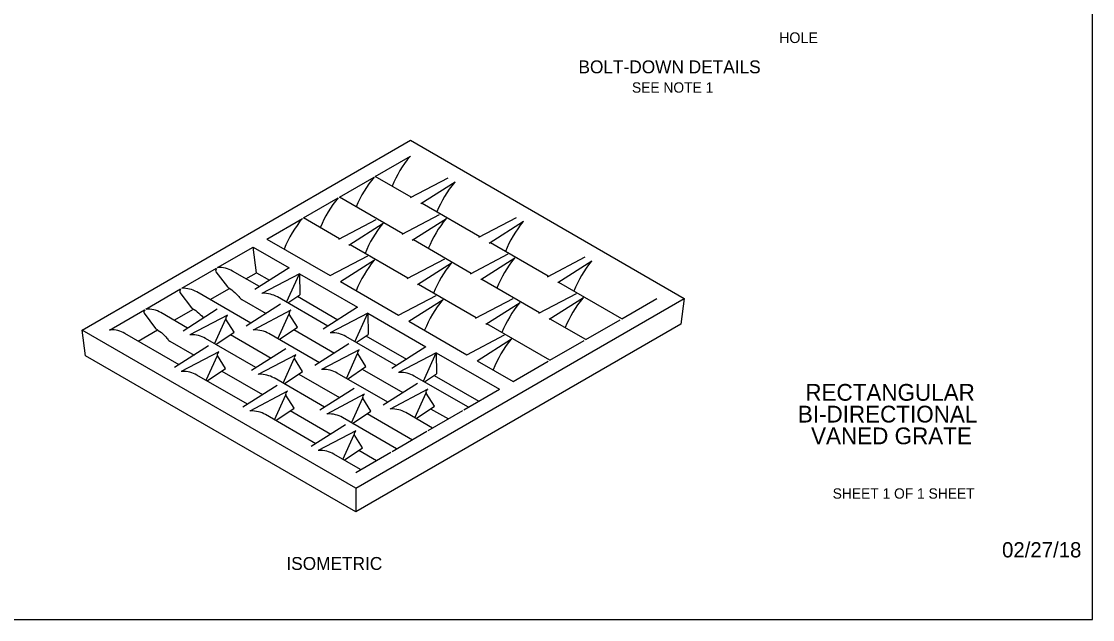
# Model space of a CAD drawing. Extents: x 99862 to 103151, y 100000 to 102076.
# Drawn here: x 101491 to 103151, y 100000 to 100926 of the extents above; entities that cross this region are included whole.
import ezdxf

# ---------------------------------------------------------------- set-up
doc = ezdxf.new("R2010")
doc.units = 0
for name, color, linetype in [('Level 1', 7, 'Continuous'), ('Level 15', 7, 'Continuous'), ('Level 20', 7, 'Continuous'), ('Level 27', 7, 'Continuous'), ('Level 6', 7, 'Continuous'), ('Level 62', 7, 'Continuous')]:
    doc.layers.add(name, color=color, linetype=linetype)

msp = doc.modelspace()

# ---------------------------------------------------------------- linework, layer by layer
at = {"layer": 'Level 1'}
msp.add_lwpolyline([(99862, 99999.5), (103151, 99999.5), (103151, 102075.5), (99862, 102075.5)], close=True, dxfattribs=at)
at = {"layer": 'Level 27'}
for p, q in [((101901.7, 100491.1), (101921.6, 100535.3)), ((102007.8, 100429.9), (102027.6, 100474.1)), ((101790.3, 100426.8), (101807.7, 100465.5)), ((101888.4, 100434.5), (101905.8, 100473.1)), ((101777.1, 100370.2), (101794.5, 100408.8)), ((101994.5, 100373.2), (102011.9, 100411.9)), ((102113.8, 100368.7), (102133.7, 100412.9)), ((101896.4, 100365.6), (101913.8, 100404.2)), ((101883.1, 100308.9), (101900.5, 100347.6)), ((102002.5, 100304.4), (102019.8, 100343)), ((102100.6, 100312), (102118, 100350.7)), ((101989.2, 100247.7), (102006.6, 100286.4))]:
    msp.add_line(p, q, dxfattribs=at)
at = {"layer": 'Level 6'}
for p, q in [((102039.3, 100686), (102093.9, 100717.5)), ((101983.7, 100653.8), (102037.7, 100685)), ((102095.1, 100653.8), (102039.3, 100686)), ((102093.9, 100653.2), (102152.3, 100683.8)), ((102109.8, 100644), (102162.9, 100677.7)), ((101928, 100621.7), (101982, 100652.9)), ((102081.8, 100597.2), (101983.7, 100653.8)), ((102201.2, 100592.6), (102111.7, 100644.2)), ((102080.7, 100596.6), (102139, 100627.2)), ((101871.2, 100588.9), (101926.3, 100620.7)), ((101983.7, 100589.5), (101928, 100621.7)), ((101982.6, 100588.9), (102040.9, 100619.5)), ((101998.5, 100579.7), (102051.5, 100613.4)), ((102096.6, 100587.4), (102149.6, 100621.1)), ((102200, 100592), (102258.3, 100622.6)), ((102215.9, 100582.8), (102268.9, 100616.5)), ((101794.9, 100544.8), (101850, 100576.7)), ((101850, 100576.7), (101905.7, 100544.5)), ((101855.3, 100536.9), (101850, 100576.7)), ((101871.2, 100588.9), (101969.3, 100532.3)), ((102089.8, 100528.3), (102000.3, 100579.9)), ((102187.9, 100535.9), (102098.4, 100587.6)), ((102307.2, 100531.3), (102217.7, 100583)), ((101969.3, 100532.3), (102027.6, 100562.9)), ((101985.2, 100523.1), (102038.3, 100556.8)), ((102088.6, 100527.7), (102147, 100558.3)), ((102186.7, 100535.3), (102245.1, 100565.9)), ((102202.7, 100526.1), (102255.7, 100559.8)), ((102306.1, 100530.7), (102364.4, 100561.4)), ((101739.2, 100512.7), (101793.2, 100543.9)), ((101905.7, 100544.5), (101852.6, 100510.8)), ((102104.5, 100518.5), (102157.6, 100552.2)), ((102322, 100521.6), (102375, 100555.2)), ((101792.3, 100538.4), (101810.1, 100514.9)), ((101859.7, 100515.4), (101818.2, 100539.3)), ((101838.9, 100527.4), (101855.3, 100536.9)), ((101855.3, 100536.9), (101875.4, 100525.3)), ((101921.6, 100535.3), (101863.2, 100504.7)), ((101921.6, 100535.3), (102011.7, 100483.3)), ((101921.6, 100535.3), (101922.1, 100502.7)), ((101985.2, 100523.1), (102075.4, 100471)), ((102294, 100474.7), (102204.5, 100526.4)), ((101683.5, 100480.5), (101737.5, 100511.7)), ((101846.5, 100458.7), (101762.5, 100507.2)), ((101783.2, 100495.2), (101813.3, 100512.6)), ((102195.8, 100467), (102106.4, 100518.7)), ((102421.2, 100465.5), (102323.8, 100521.8)), ((101736.6, 100506.3), (101754.4, 100482.7)), ((101832.3, 100495.2), (101869.9, 100473.5)), ((101965.8, 100454.1), (101887.6, 100499.3)), ((101903.5, 100490.1), (101922.1, 100502.7)), ((101918.6, 100500.3), (101981.4, 100464)), ((102009.1, 100203.1), (102518.2, 100497.1)), ((102075.4, 100471), (102133.7, 100501.6)), ((102091.3, 100461.8), (102144.3, 100495.5)), ((102194.7, 100466.4), (102253, 100497.1)), ((102210.6, 100457.3), (102263.6, 100490.9)), ((102292.8, 100474.1), (102351.1, 100504.7)), ((102308.7, 100464.9), (102361.8, 100498.6)), ((102421.2, 100465.5), (102475.8, 100497.1)), ((101627.2, 100448.1), (101681.8, 100479.6)), ((101680.9, 100474.1), (101698.7, 100450.6)), ((101748.4, 100451.1), (101706.8, 100475)), ((101727.5, 100463.1), (101757.6, 100480.4)), ((101794.3, 100480.2), (101741.3, 100446.5)), ((101892.4, 100487.9), (101839.4, 100454.2)), ((101908.3, 100478.7), (101850, 100448.1)), ((102011.7, 100483.3), (101958.7, 100449.6)), ((102027.6, 100474.1), (101969.3, 100443.5)), ((102027.6, 100474.1), (102117.8, 100422)), ((102027.6, 100474.1), (102028.2, 100441.4)), ((101810.2, 100471), (101751.9, 100440.4)), ((101820.5, 100445), (101807.9, 100465.1)), ((101918.6, 100452.6), (101906, 100472.8)), ((102091.3, 100461.8), (102181.4, 100409.8)), ((102309.8, 100401.2), (102212.4, 100457.5)), ((102365.5, 100433.4), (102310.5, 100465.1)), ((102365.5, 100433.4), (102418.7, 100464.1)), ((102009.1, 100203.1), (101584.8, 100448.1)), ((101735.1, 100394.4), (101651.2, 100442.9)), ((101671.8, 100430.9), (101701.9, 100448.3)), ((101792.1, 100425.8), (101820.5, 100445)), ((101814.7, 100441.1), (101877.8, 100404.7)), ((101952.6, 100397.5), (101874.3, 100442.6)), ((101890.2, 100433.5), (101918.6, 100452.6)), ((101912.9, 100448.7), (101975.9, 100412.3)), ((102009.5, 100428.9), (102028.2, 100441.4)), ((102181.4, 100409.8), (102239.8, 100440.4)), ((101720.9, 100430.9), (101758.5, 100409.2)), ((101781, 100423.6), (101728, 100389.9)), ((101854.4, 100389.8), (101776.2, 100435)), ((101998.5, 100426.6), (101945.4, 100393)), ((102071.9, 100392.9), (101993.6, 100438.1)), ((102024.7, 100439.1), (102087.5, 100402.8)), ((102197.4, 100400.6), (102250.4, 100434.3)), ((102309.8, 100401.2), (102363.1, 100432)), ((101797, 100414.4), (101738.6, 100383.8)), ((101807.2, 100388.3), (101794.6, 100408.5)), ((101900.4, 100419), (101847.3, 100385.3)), ((101916.3, 100409.8), (101857.9, 100379.2)), ((102014.4, 100417.4), (101956.1, 100386.8)), ((102024.7, 100391.4), (102012.1, 100411.6)), ((102117.8, 100422), (102064.8, 100388.4)), ((102133.7, 100412.9), (102075.4, 100382.2)), ((102133.7, 100412.9), (102231.8, 100356.2)), ((102133.7, 100412.9), (102134.2, 100380.2)), ((101926.6, 100383.7), (101913.9, 100403.9)), ((101996.3, 100372.2), (102024.7, 100391.4)), ((102197.4, 100400.6), (102253, 100368.5)), ((102253, 100368.5), (102307.4, 100399.8)), ((101841.2, 100333.2), (101762.9, 100378.3)), ((101778.9, 100369.2), (101807.2, 100388.3)), ((101801.5, 100384.4), (101864.6, 100348)), ((101960.5, 100328.6), (101882.3, 100373.8)), ((101898.2, 100364.6), (101926.6, 100383.7)), ((101920.8, 100379.8), (101983.9, 100343.4)), ((102058.6, 100336.2), (101980.4, 100381.4)), ((102018.9, 100387.5), (102082, 100351.1)), ((102183.6, 100328.4), (102099.7, 100376.8)), ((102115.6, 100367.6), (102134.2, 100380.2)), ((102130.7, 100377.8), (102200, 100337.8)), ((101887.1, 100362.3), (101834.1, 100328.7)), ((102006.4, 100357.7), (101953.4, 100324.1)), ((102104.5, 100365.4), (102051.5, 100331.7)), ((101903, 100353.1), (101844.7, 100322.5)), ((101913.3, 100327.1), (101900.7, 100347.3)), ((102022.3, 100348.6), (101964, 100317.9)), ((102032.6, 100322.5), (102020, 100342.7)), ((102120.5, 100356.2), (102062.1, 100325.6)), ((102130.8, 100330.1), (102118.1, 100350.3)), ((102176.7, 100324.4), (102231.8, 100356.2)), ((101884.9, 100307.9), (101913.3, 100327.1)), ((102102.4, 100311), (102130.8, 100330.1)), ((102125, 100326.2), (102152.5, 100310.4)), ((101947.3, 100271.9), (101869, 100317.1)), ((101907.6, 100323.2), (101970.6, 100286.8)), ((102072.2, 100264.1), (101988.3, 100312.5)), ((102004.2, 100303.3), (102032.6, 100322.5)), ((102026.9, 100318.6), (102096.8, 100278.2)), ((102127.9, 100296.2), (102086.4, 100320.2)), ((102121, 100292.2), (102175, 100323.4)), ((101993.2, 100301.1), (101940.1, 100267.4)), ((102009.1, 100291.9), (101950.7, 100261.3)), ((102065.3, 100260.1), (102119.3, 100291.3)), ((102019.4, 100265.8), (102006.7, 100286)), ((101991, 100246.7), (102019.4, 100265.8)), ((102009.1, 100227.6), (102063.6, 100259.1)), ((102013.6, 100261.9), (102041.1, 100246.1)), ((102016.6, 100231.9), (101975.1, 100255.9)), ((102009.1, 100203.1), (102009.1, 100166.4))]:
    msp.add_line(p, q, dxfattribs=at)
for points in [[(102009.1, 100166.4), (101590.1, 100408.3), (101584.8, 100448.1), (102093.9, 100742), (102518.2, 100497.1), (102512.9, 100457.3), (102009.1, 100166.4)], [(101811.1, 100514), (101812.4, 100513.2), (101814.4, 100511.8), (101816.7, 100510.2), (101819, 100508.3), (101821.5, 100506.3), (101823.8, 100504.1), (101825.9, 100502), (101827.7, 100500), (101828.9, 100498.5), (101829.3, 100497.9)], [(101755.6, 100481.7), (101756.7, 100481), (101758.7, 100479.7), (101761, 100478.1), (101763.4, 100476.2), (101765.8, 100474.1), (101768.1, 100472), (101770.2, 100469.9), (101772, 100467.9), (101773, 100466.7)], [(101700, 100449.5), (101701, 100448.9), (101703, 100447.5), (101705.3, 100445.9), (101707.7, 100444), (101710.1, 100442), (101712.4, 100439.8), (101714.5, 100437.7), (101716.3, 100435.7), (101717.5, 100434.2), (101718, 100433.6)]]:
    msp.add_lwpolyline(points, dxfattribs=at)
for centre in [(101837, 100503.3), (101725.6, 100439)]:
    msp.add_arc(centre, 9.38, 215.1039, 240, dxfattribs=at)
for centre, major_axis, ratio, start_param, end_param in [((102128.9, 100653.4), (45.9, 94.6), 0.619773, 1.169443, 1.684701), ((102094.1, 100714.3), (1.64, 3.38), 0.619773, 0.740646, 1.169443), ((102073.2, 100621.3), (45.9, 94.6), 0.619773, 1.161599, 1.684701), ((102193.5, 100616.2), (46.2, 94.5), 0.567299, 1.175034, 1.690292), ((102163, 100674.6), (1.65, 3.37), 0.567299, 0.746237, 1.175034), ((102017.5, 100589.1), (45.9, 94.6), 0.619773, 1.161599, 1.684701), ((102109.9, 100640.9), (1.65, 3.37), 0.567299, 6.244024, 7.029423), ((101961.9, 100557), (45.9, 94.6), 0.619773, 1.161599, 1.695304), ((102082.1, 100551.9), (46.2, 94.5), 0.567299, 1.175034, 1.690292), ((102051.6, 100610.3), (1.65, 3.37), 0.567299, 0.746237, 1.175034), ((102180.2, 100559.5), (46.2, 94.5), 0.567299, 1.175034, 1.690292), ((102149.7, 100617.9), (1.65, 3.37), 0.567299, 0.746237, 1.175034), ((102299.6, 100554.9), (46.2, 94.5), 0.567299, 1.175034, 1.690292), ((102269, 100613.4), (1.65, 3.37), 0.567299, 0.746237, 1.175034), ((101998.6, 100576.6), (1.65, 3.37), 0.567299, 6.244024, 7.029423), ((102096.7, 100584.3), (1.65, 3.37), 0.567299, 6.244024, 7.029423), ((102216, 100579.7), (1.65, 3.37), 0.567299, 6.244024, 7.029423), ((102038.3, 100553.7), (1.65, 3.37), 0.567299, 0.746237, 1.175034), ((102286.3, 100498.3), (46.2, 94.5), 0.567299, 1.175034, 1.690292), ((102255.8, 100556.7), (1.65, 3.37), 0.567299, 0.746237, 1.175034), ((101794.5, 100541.3), (1.64, 3.38), 0.619773, 1.141912, 2.835041), ((101769.7, 100446.1), (45.9, 94.6), 0.619773, 6.238433, 6.602879), ((102068.9, 100495.2), (46.2, 94.5), 0.567299, 1.175034, 1.700895), ((102188.2, 100490.6), (46.2, 94.5), 0.567299, 1.175034, 1.690292), ((102157.7, 100549.1), (1.65, 3.37), 0.567299, 0.746237, 1.175034), ((102405.6, 100493.7), (46.2, 94.5), 0.567299, 1.175034, 1.690292), ((102375.1, 100552.1), (1.65, 3.37), 0.567299, 0.746237, 1.175034), ((102202.7, 100523), (1.65, 3.37), 0.567299, 6.244024, 7.029423), ((101738.8, 100509.2), (1.64, 3.38), 0.619773, 1.14206, 2.835041), ((101714.1, 100413.9), (45.9, 94.6), 0.619773, 6.238433, 6.602879), ((101815.6, 100522.2), (4.1, 8.45), 0.619773, 2.835041, 3.059939), ((102104.6, 100515.4), (1.65, 3.37), 0.567299, 6.244024, 7.029423), ((102322.1, 100518.4), (1.65, 3.37), 0.567299, 6.244024, 7.029423), ((101863.3, 100501.6), (-1.92, -3.22), 0.624048, 3.506595, 3.935392), ((101834.3, 100408.8), (-53.7, -90.2), 0.624048, 3.149994, 3.506595), ((102174.9, 100434), (46.2, 94.5), 0.567299, 1.175034, 1.700895), ((102144.4, 100492.4), (1.65, 3.37), 0.567299, 0.746237, 1.175034), ((102294.3, 100429.4), (46.2, 94.5), 0.567299, 1.175034, 1.690292), ((102263.7, 100487.8), (1.65, 3.37), 0.567299, 0.746237, 1.175034), ((102392.4, 100437), (46.2, 94.5), 0.567299, 1.175034, 1.690292), ((102361.8, 100495.5), (1.65, 3.37), 0.567299, 0.746237, 1.175034), ((101683.1, 100477), (1.64, 3.38), 0.619773, 1.14206, 2.835041), ((101658.4, 100381.8), (45.9, 94.6), 0.619773, 6.238433, 6.602879), ((101759.9, 100490), (4.1, 8.45), 0.619773, 2.835041, 3.113262), ((101908.4, 100475.6), (-1.92, -3.22), 0.624048, 3.935392, 5.854131), ((101810.3, 100467.9), (-1.92, -3.22), 0.624048, 3.935392, 5.854131), ((101810.1, 100468.1), (1.82, 3.28), 0.5012, 2.695193, 2.870849), ((101908.2, 100475.7), (1.82, 3.28), 0.5012, 2.695193, 2.870849), ((102210.7, 100454.1), (1.65, 3.37), 0.567299, 6.244024, 7.029423), ((102308.8, 100461.8), (1.65, 3.37), 0.567299, 6.244024, 7.029423), ((101627.4, 100444.9), (1.64, 3.38), 0.619773, 0.31185, 0.740646), ((101602.7, 100349.6), (45.9, 94.6), 0.619773, 6.238433, 6.595035), ((101704.2, 100457.9), (4.1, 8.45), 0.619773, 2.835041, 3.113262), ((101752, 100437.3), (-1.92, -3.22), 0.624048, 3.506595, 3.935392), ((101723, 100344.5), (-53.7, -90.2), 0.624048, 3.149994, 3.506595), ((101850.1, 100445), (-1.92, -3.22), 0.624048, 3.506595, 3.935392), ((101821.1, 100352.1), (-53.7, -90.2), 0.624048, 3.149994, 3.506595), ((101969.4, 100440.4), (-1.92, -3.22), 0.624048, 3.506595, 3.935392), ((101940.4, 100347.6), (-53.7, -90.2), 0.624048, 3.149994, 3.506595), ((102281, 100372.7), (46.2, 94.5), 0.567299, 1.175034, 1.700895), ((102250.5, 100431.2), (1.65, 3.37), 0.567299, 0.746237, 1.175034), ((101797, 100411.3), (-1.92, -3.22), 0.624048, 3.935392, 5.854131), ((101796.8, 100411.4), (1.82, 3.28), 0.5012, 2.695193, 2.870849), ((101916.4, 100406.7), (-1.92, -3.22), 0.624048, 3.935392, 5.854131), ((102014.5, 100414.3), (-1.92, -3.22), 0.624048, 3.935392, 5.854131), ((102014.2, 100414.5), (1.82, 3.28), 0.5012, 2.695193, 2.870849), ((101916.1, 100406.8), (1.82, 3.28), 0.5012, 2.695193, 2.870849), ((101738.7, 100380.7), (-1.92, -3.22), 0.624048, 3.506595, 3.935392), ((101709.7, 100287.8), (-53.7, -90.2), 0.624048, 3.149994, 3.506595), ((101858, 100376.1), (-1.92, -3.22), 0.624048, 3.506595, 3.935392), ((101829, 100283.3), (-53.7, -90.2), 0.624048, 3.149994, 3.506595), ((101956.1, 100383.7), (-1.92, -3.22), 0.624048, 3.506595, 3.935392), ((101927.1, 100290.9), (-53.7, -90.2), 0.624048, 3.149994, 3.506595), ((102075.5, 100379.1), (-1.92, -3.22), 0.624048, 3.506595, 3.935392), ((102046.5, 100286.3), (-53.7, -90.2), 0.624048, 3.149994, 3.506595), ((101903.1, 100350), (-1.92, -3.22), 0.624048, 3.935392, 5.854131), ((101902.9, 100350.2), (1.82, 3.28), 0.5012, 2.695193, 2.870849), ((102022.4, 100345.4), (-1.92, -3.22), 0.624048, 3.935392, 5.854131), ((102022.2, 100345.6), (1.82, 3.28), 0.5012, 2.695193, 2.870849), ((102120.5, 100353.1), (-1.92, -3.22), 0.624048, 3.935392, 5.854131), ((102120.3, 100353.2), (1.82, 3.28), 0.5012, 2.695193, 2.870849), ((102062.2, 100322.5), (-1.92, -3.22), 0.624048, 3.506595, 3.935392), ((102033.2, 100229.7), (-53.7, -90.2), 0.624048, 3.149994, 3.506595), ((101844.8, 100319.4), (-1.92, -3.22), 0.624048, 3.506595, 3.935392), ((101815.8, 100226.6), (-53.7, -90.2), 0.624048, 3.149994, 3.506595), ((101964.1, 100314.8), (-1.92, -3.22), 0.624048, 3.506595, 3.935392), ((101935.1, 100222), (-53.7, -90.2), 0.624048, 3.149994, 3.506595), ((102009.2, 100288.8), (-1.92, -3.22), 0.624048, 3.935392, 5.854131), ((102008.9, 100288.9), (1.82, 3.28), 0.5012, 2.695193, 2.870849), ((101950.8, 100258.2), (-1.92, -3.22), 0.624048, 3.506595, 3.935392), ((101921.8, 100165.4), (-53.7, -90.2), 0.624048, 3.149994, 3.506595)]:
    msp.add_ellipse(centre, major_axis=major_axis, ratio=ratio, start_param=start_param, end_param=end_param, dxfattribs=at)

# ---------------------------------------------------------------- texts
at = {"layer": 'Level 1'}
msp.add_text('HOLE', height=16.5, dxfattribs=at).set_placement((102665.1, 100892.7))
at = {"layer": 'Level 15'}
msp.add_text('02/27/18', height=23.62, dxfattribs=at).set_placement((103010.7, 100095.8))
at = {"layer": 'Level 20'}
for s, p in [('BOLT-DOWN DETAILS', (102354.2, 100845.8)), ('ISOMETRIC', (101901.5, 100076.4))]:
    msp.add_text(s, height=20, dxfattribs=at).set_placement(p)
at = {"layer": 'Level 62'}
for s, height, p in [('SEE NOTE 1', 16, (102437.1, 100815.8)), ('RECTANGULAR', 26, (102705.8, 100338.5)), ('BI-DIRECTIONAL', 26, (102694.2, 100304.8)), ('VANED GRATE', 26, (102714.7, 100271.1)), ('SHEET 1 OF 1 SHEET', 16, (102748.2, 100186.8))]:
    msp.add_text(s, height=height, dxfattribs=at).set_placement(p)

doc.saveas('drawing.dxf')
